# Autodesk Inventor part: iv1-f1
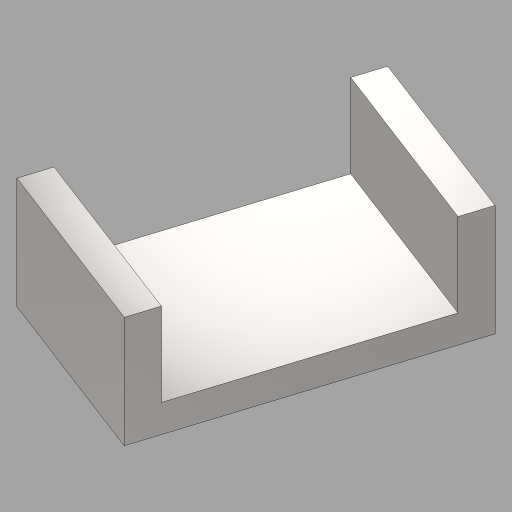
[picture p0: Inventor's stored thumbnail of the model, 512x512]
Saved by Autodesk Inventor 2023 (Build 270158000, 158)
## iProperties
Created: 2004-09
Part Number: iv1-f1
Document SubType Name: Modeling
Designer: Lars Bertram Pedersen
Manufacturer: Standard
Standards Organization: Custom
Material: Steel, Mild
Density: 7.85 g/cm^3
Appearance: Semi-Polished
Mass: 94.2 g
Surface Area: 59 cm^2
Volume: 12 cm^3
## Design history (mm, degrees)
sketch "Sketch1"
  geometry: L1 (0, 0)-(50, 0); L2 (50, 0)-(50, 20); L3 (50, 20)-(45, 20); L4 (45, 20)-(45, 5); L5 (45, 5)-(5, 5); L6 (5, 5)-(5, 20); L7 (5, 20)-(0, 20); L8 (0, 20)-(0, 0); 1 further point
  constraints: 16 end point, 5 perpendicular, 2 parallel, 1 coincident, 1 collinear, 1 horizontal
  dimensions: "d11" = 50 distance of L1.start L1.end; "d12" = 20 distance of L7.end L1.start; "d13" = 5 distance of L2.end L3.end; "d14" = 5 distance of L6.end L7.end; "d15" = 5 distance between parallel lines of L1 L5
extrude "Extrusion1" new body sketch "Sketch1" distance "d9" = 30; taper "d10" = 0 deg
body "Solid1"
